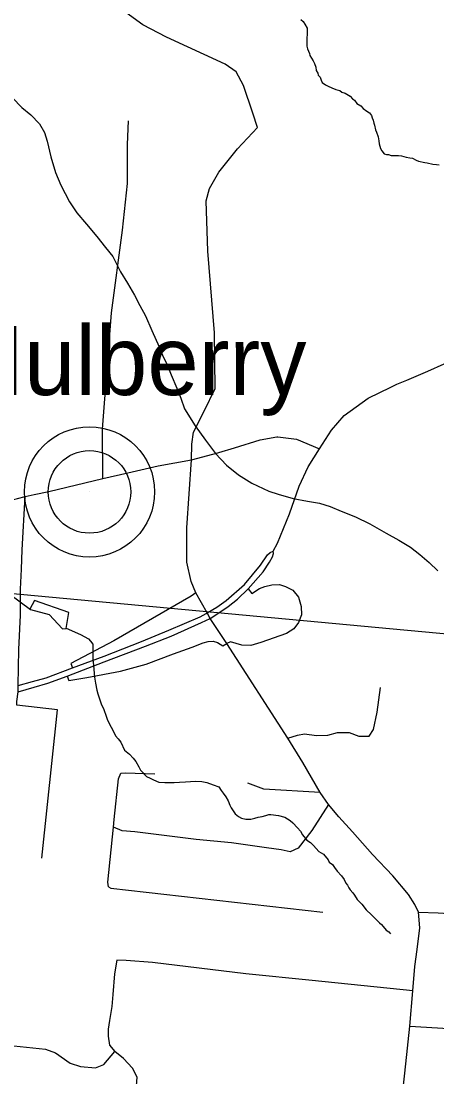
# Model space of a CAD drawing. Extents: x 0 to 34, y 0 to 22.
# Drawn here: x 7.641 to 7.879, y 19.556 to 20.159 of the extents above; entities that cross this region are included whole.
import ezdxf

# ---------------------------------------------------------------- set-up
doc = ezdxf.new("R2010")
doc.units = 0
for name, color, linetype in [('GM_X_County_Road', 7, 'Continuous'), ('GM_X_Interchange_Ramps', 7, 'Continuous'), ('GM_X_Minor_Lake', 7, 'Continuous'), ('GM_X_Minor_River', 7, 'Continuous'), ('GM_X_Rail_Line', 7, 'Continuous'), ('GM_X_State_Route', 7, 'Continuous'), ('GM_X_Township_Road', 7, 'Continuous'), ('GM_X_Unincorporated', 7, 'Continuous'), ('GM_X_Unincorporated_Location', 7, 'Continuous'), ('GM_X_Unincorporated_Text', 7, 'Continuous')]:
    doc.layers.add(name, color=color, linetype=linetype)

msp = doc.modelspace()

# ---------------------------------------------------------------- linework, layer by layer
at = {"layer": 'GM_X_County_Road'}
for points in [[(7.73843, 19.90847), (7.75355, 19.91233), (7.75403, 19.91248), (7.76303, 19.91527), (7.77771, 19.91983), (7.78722, 19.92152)], [(7.78722, 19.92152), (7.78772, 19.9216), (7.79852, 19.92026), (7.81158, 19.91469)], [(7.68784, 19.89767), (7.70218, 19.90099), (7.71937, 19.90491), (7.73843, 19.90847)], [(7.85261, 19.48627), (7.86089, 19.56343), (7.86331, 19.58497), (7.86502, 19.60508), (7.86602, 19.61906), (7.86744, 19.62876), (7.86887, 19.64117), (7.86816, 19.65001), (7.86609, 19.65451), (7.86238, 19.66007), (7.85354, 19.67076), (7.84184, 19.68303), (7.83043, 19.69601), (7.82273, 19.70443), (7.81674, 19.71156), (7.81203, 19.7184), (7.80205, 19.73552), (7.79352, 19.74936), (7.7586, 19.80343), (7.74921, 19.81782), (7.74746, 19.82097), (7.74102, 19.83248), (7.73832, 19.83882), (7.73576, 19.84991), (7.73576, 19.86945), (7.73843, 19.90847)], [(7.64851, 19.88856), (7.65705, 19.89033), (7.68784, 19.89767)], [(7.59298, 19.87576), (7.60605, 19.87847), (7.62524, 19.8829), (7.63912, 19.88631), (7.64349, 19.88752), (7.64851, 19.88856)]]:
    msp.add_lwpolyline(points, dxfattribs=at)
at = {"layer": 'GM_X_Interchange_Ramps'}
for points in [[(7.77094, 19.83479), (7.77295, 19.83205), (7.77728, 19.83494), (7.78037, 19.8361), (7.7844, 19.8369), (7.78867, 19.83715), (7.79219, 19.83596), (7.79629, 19.83388), (7.79963, 19.83001), (7.8012, 19.82468), (7.80126, 19.8199), (7.79952, 19.81547), (7.7969, 19.81184), (7.79267, 19.80919), (7.77808, 19.80412), (7.77235, 19.80239), (7.7672, 19.8025), (7.76067, 19.80449), (7.7586, 19.80343)], [(7.74102, 19.83248), (7.73831, 19.8306), (7.69418, 19.80503), (7.66945, 19.79213), (7.6705, 19.78953)], [(7.66745, 19.78491), (7.66833, 19.78234), (7.6787, 19.78404), (7.69793, 19.78772), (7.71258, 19.79175), (7.72816, 19.79763), (7.73878, 19.80143), (7.74516, 19.80384), (7.74805, 19.80469), (7.75085, 19.80477), (7.75332, 19.80401), (7.75646, 19.80214), (7.7586, 19.80343)]]:
    msp.add_lwpolyline(points, dxfattribs=at)
at = {"layer": 'GM_X_Minor_Lake'}
for points in [[(7.63467, 19.8317), (7.64643, 19.82294), (7.65717, 19.82007), (7.66477, 19.81178), (7.66686, 19.81212), (7.66837, 19.82119)], [(7.66837, 19.82119), (7.6488, 19.82801), (7.64609, 19.82319)]]:
    msp.add_lwpolyline(points, dxfattribs=at)
at = {"layer": 'GM_X_Minor_River'}
for points in [[(7.801, 20.15983), (7.8023, 20.15865), (7.80321, 20.15711), (7.80448, 20.15481), (7.80464, 20.15366), (7.80458, 20.1512), (7.80434, 20.14931), (7.80444, 20.14589), (7.80441, 20.14457), (7.80475, 20.14304), (7.80582, 20.14036), (7.80617, 20.13921), (7.80709, 20.13786), (7.808, 20.13632), (7.80872, 20.13478), (7.80943, 20.13268), (7.80976, 20.13077), (7.81067, 20.12923), (7.81083, 20.12809), (7.81194, 20.12692), (7.81247, 20.1252), (7.81319, 20.12386), (7.81506, 20.12248), (7.81656, 20.12187), (7.81862, 20.12087), (7.82088, 20.11986), (7.82314, 20.11923), (7.82445, 20.11844), (7.82633, 20.11782), (7.82914, 20.11604), (7.83043, 20.11449), (7.83155, 20.1137), (7.83302, 20.11196), (7.83527, 20.11057), (7.83656, 20.10902), (7.8386, 20.10745), (7.8401, 20.10646), (7.84139, 20.1051), (7.84174, 20.10377), (7.84228, 20.10243), (7.84261, 20.10071), (7.84296, 20.09956), (7.84365, 20.09689), (7.84419, 20.09555), (7.84507, 20.09287), (7.84558, 20.09058), (7.84573, 20.08887), (7.84642, 20.0862), (7.84715, 20.08485), (7.84862, 20.08311), (7.84994, 20.08269), (7.85108, 20.08266), (7.85259, 20.08224), (7.85677, 20.08213), (7.85847, 20.0819), (7.86111, 20.08126), (7.86319, 20.08083), (7.8647, 20.0806), (7.86677, 20.0796), (7.86808, 20.07899), (7.87186, 20.07814), (7.87318, 20.07791), (7.87639, 20.07726), (7.87847, 20.07702), (7.87999, 20.07679)], [(7.63613, 20.1151), (7.64152, 20.10968), (7.64674, 20.10541), (7.65156, 20.1002), (7.65449, 20.0954), (7.65609, 20.09044), (7.65818, 20.08149), (7.66084, 20.07252), (7.66372, 20.06526), (7.66883, 20.05568), (7.67287, 20.04935), (7.67843, 20.04299), (7.68434, 20.03586), (7.68933, 20.02969), (7.69359, 20.02449), (7.69795, 20.01569), (7.70199, 20.00935), (7.70583, 20.00245), (7.70893, 19.99651), (7.71222, 19.99057), (7.71584, 19.98216), (7.72001, 19.97298), (7.72199, 19.9682), (7.72453, 19.96265), (7.72688, 19.95692), (7.73013, 19.94928), (7.73229, 19.94355), (7.73444, 19.93744), (7.74049, 19.92784), (7.74639, 19.91958), (7.75211, 19.91207), (7.75841, 19.90531), (7.76531, 19.89987), (7.77298, 19.89498), (7.78274, 19.89043), (7.78802, 19.88882), (7.7965, 19.88638), (7.8048, 19.8847), (7.8116, 19.88362), (7.81763, 19.8818), (7.82401, 19.87902), (7.8321, 19.87583), (7.84036, 19.87188), (7.84972, 19.86658), (7.85703, 19.86245), (7.86358, 19.85854), (7.86899, 19.85426), (7.8742, 19.8498), (7.87922, 19.84496)], [(7.66688, 19.81224), (7.67514, 19.80872), (7.67964, 19.80614), (7.68074, 19.80479), (7.68203, 19.80305), (7.68219, 19.80191), (7.68207, 19.79698), (7.68218, 19.79413), (7.68234, 19.7928), (7.68249, 19.79109), (7.68261, 19.78862), (7.68307, 19.78425), (7.68356, 19.78082), (7.68441, 19.77682), (7.68492, 19.77472), (7.68687, 19.76898), (7.68831, 19.76572), (7.68973, 19.76208), (7.69026, 19.76036), (7.69171, 19.75748), (7.69352, 19.75402), (7.69514, 19.75076), (7.69662, 19.74901), (7.69809, 19.74708), (7.70026, 19.74266), (7.70305, 19.74031), (7.70508, 19.73798), (7.70674, 19.73604), (7.70837, 19.73297), (7.70928, 19.73124), (7.71279, 19.72754), (7.71485, 19.72654), (7.71673, 19.72555), (7.71974, 19.72433), (7.72315, 19.72405), (7.72866, 19.7241), (7.7317, 19.72421), (7.73512, 19.7245), (7.74083, 19.72491), (7.74443, 19.72463), (7.74727, 19.72418), (7.75084, 19.72276), (7.75404, 19.72154), (7.75551, 19.7196), (7.75661, 19.71806), (7.75808, 19.71593), (7.75935, 19.71362), (7.76043, 19.71113), (7.76115, 19.70959), (7.76334, 19.70613), (7.76539, 19.70474), (7.76708, 19.70375), (7.76953, 19.70312), (7.77238, 19.70324), (7.77467, 19.70374), (7.77658, 19.70426), (7.77888, 19.70477), (7.78098, 19.70529), (7.7827, 19.70581), (7.78384, 19.70578), (7.78819, 19.70529), (7.79178, 19.70424)], [(7.79178, 19.70424), (7.79477, 19.70246), (7.79644, 19.70109), (7.79903, 19.69818), (7.80069, 19.69624), (7.80197, 19.69431), (7.80436, 19.69121), (7.80642, 19.68983), (7.80827, 19.68808), (7.81123, 19.68478), (7.81385, 19.68319), (7.81661, 19.6799), (7.81715, 19.67855), (7.81902, 19.67737), (7.82011, 19.67563), (7.82177, 19.6735), (7.82417, 19.67079), (7.82563, 19.66866), (7.82672, 19.66655), (7.82764, 19.66539), (7.82837, 19.66404), (7.8291, 19.66289), (7.83057, 19.66114), (7.83168, 19.65978), (7.83313, 19.65728), (7.83572, 19.65456), (7.8383, 19.65146), (7.84127, 19.64854), (7.84331, 19.64659), (7.8459, 19.64387), (7.84702, 19.64308), (7.84794, 19.64192), (7.84978, 19.63978), (7.85128, 19.6388), (7.8522, 19.63763)]]:
    msp.add_lwpolyline(points, dxfattribs=at)
at = {"layer": 'GM_X_Rail_Line'}
msp.add_lwpolyline([(8.9, 19.7176), (8.69584, 19.73341), (7.47033, 19.84735), (7.26736, 19.78133), (7.23591, 19.76162), (7.19492, 19.71716), (7.16666, 19.69799), (6.88858, 19.5517)], dxfattribs=at)
at = {"layer": 'GM_X_State_Route'}
for points in [[(7.86146, 19.95391), (7.87358, 19.95904), (7.88275, 19.96311), (7.9044, 19.97168), (7.91682, 19.97713)], [(7.8523, 19.94983), (7.85587, 19.95154), (7.86146, 19.95391)], [(7.81158, 19.91469), (7.81837, 19.92525), (7.82576, 19.93367), (7.83936, 19.94365), (7.8523, 19.94983)], [(7.78511, 19.8562), (7.78758, 19.86073), (7.79441, 19.87755), (7.79992, 19.89341), (7.80509, 19.90429), (7.81158, 19.91469)], [(7.63946, 19.77949), (7.64769, 19.78175), (7.65542, 19.78397), (7.6705, 19.78953), (7.68848, 19.79628), (7.70991, 19.80467), (7.72548, 19.81102), (7.7434, 19.81869), (7.74691, 19.82064), (7.74746, 19.82097), (7.75302, 19.82431), (7.75832, 19.82814), (7.76883, 19.83713), (7.77791, 19.84822), (7.78197, 19.85404), (7.78338, 19.85551), (7.78511, 19.8562)], [(7.77094, 19.83479), (7.77942, 19.84444), (7.78312, 19.84987), (7.78482, 19.85298), (7.78528, 19.85496), (7.78511, 19.8562)], [(7.63943, 19.77593), (7.64856, 19.77864), (7.65629, 19.78086), (7.66745, 19.78491), (7.68862, 19.79295), (7.71214, 19.80192), (7.72678, 19.80776), (7.74422, 19.81541), (7.74921, 19.81782), (7.75409, 19.821), (7.75943, 19.8247), (7.76478, 19.82873), (7.77094, 19.83479)]]:
    msp.add_lwpolyline(points, dxfattribs=at)
at = {"layer": 'GM_X_Township_Road'}
for points in [[(7.73843, 19.90847), (7.73862, 19.91737), (7.73953, 19.92411), (7.74575, 19.93619), (7.75202, 19.94904), (7.75163, 19.98089), (7.74779, 20.02757), (7.74692, 20.05621), (7.74868, 20.06338), (7.75409, 20.07267), (7.76478, 20.08597), (7.77627, 20.09817), (7.77351, 20.10645), (7.76821, 20.12209), (7.76407, 20.12992), (7.75763, 20.13429), (7.72415, 20.14978), (7.71066, 20.15684), (7.67453, 20.1832), (7.65423, 20.19768), (7.64745, 20.20177)], [(7.68784, 19.89767), (7.68755, 19.92593), (7.69269, 19.9924), (7.69896, 20.03947), (7.70181, 20.06628), (7.70181, 20.08853), (7.70239, 20.10194)], [(7.65289, 19.68097), (7.66188, 19.76554), (7.63868, 19.76836), (7.63875, 19.7704), (7.63943, 19.77593), (7.63946, 19.77949), (7.63981, 19.80002), (7.64072, 19.81971), (7.64084, 19.83449), (7.6413, 19.84585), (7.64177, 19.85703), (7.64349, 19.88752)], [(7.79352, 19.74936), (7.79905, 19.75121), (7.80305, 19.75192), (7.80998, 19.75094), (7.81645, 19.75121), (7.82188, 19.75263), (7.82858, 19.75263), (7.834, 19.75064), (7.83999, 19.75049), (7.84255, 19.75435), (7.84455, 19.76433), (7.8465, 19.77833)], [(7.69114, 19.66446), (7.6906, 19.66711), (7.69385, 19.69851), (7.69432, 19.703), (7.69672, 19.72617), (7.69807, 19.72939)], [(7.69807, 19.72939), (7.70072, 19.72956), (7.71755, 19.72906)], [(7.81203, 19.7184), (7.7798, 19.72026), (7.77067, 19.72382)], [(7.81674, 19.71156), (7.80722, 19.69662), (7.79934, 19.6866), (7.79477, 19.6846), (7.78978, 19.6856), (7.78137, 19.68688), (7.7614, 19.68959), (7.74114, 19.69159), (7.70606, 19.69601), (7.69882, 19.69654), (7.69385, 19.69851)], [(7.69114, 19.66446), (7.69246, 19.66369), (7.81357, 19.64999)], [(7.86816, 19.65001), (7.8795, 19.64966), (7.89162, 19.64894), (7.93255, 19.64561)], [(7.86502, 19.60508), (7.80744, 19.61111), (7.76958, 19.61486), (7.71626, 19.62132), (7.70117, 19.62245), (7.69583, 19.62273), (7.69452, 19.61486), (7.69349, 19.60296), (7.69302, 19.59621), (7.6917, 19.58827), (7.69091, 19.58316), (7.69088, 19.57918), (7.69159, 19.57406), (7.69461, 19.57053)], [(7.86331, 19.58497), (7.91999, 19.58144), (8.11442, 19.56312), (8.1297, 19.56111), (8.1392, 19.55986)], [(7.56385, 19.57212), (7.56622, 19.57119), (7.5799, 19.57025), (7.59171, 19.5695), (7.59909, 19.56976), (7.60764, 19.574), (7.61645, 19.5755), (7.63332, 19.57418), (7.65506, 19.57175), (7.66069, 19.56969), (7.66908, 19.56387), (7.67512, 19.562), (7.68355, 19.56125), (7.68829, 19.5631), (7.69461, 19.57053)], [(7.70098, 19.49509), (7.70492, 19.53389), (7.70586, 19.54045), (7.70661, 19.54804), (7.70707, 19.55094), (7.70736, 19.55582), (7.70473, 19.56106), (7.69958, 19.56641), (7.69461, 19.57053)]]:
    msp.add_lwpolyline(points, dxfattribs=at)
at = {"layer": 'GM_X_Unincorporated'}
for radius in [0.0372, 0.02358]:
    msp.add_circle((7.68021, 19.89006), radius, dxfattribs=at)
at = {"layer": 'GM_X_Unincorporated_Location'}
msp.add_line((7.68021, 19.89006), (7.68021, 19.89006), dxfattribs=at)

# ---------------------------------------------------------------- texts
at = {"layer": 'GM_X_Unincorporated_Text'}
msp.add_text('Mulberry', height=0.039489, rotation=0.00001, dxfattribs=at).set_placement((7.59878, 19.94539))

doc.saveas('drawing.dxf')
